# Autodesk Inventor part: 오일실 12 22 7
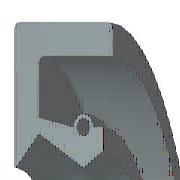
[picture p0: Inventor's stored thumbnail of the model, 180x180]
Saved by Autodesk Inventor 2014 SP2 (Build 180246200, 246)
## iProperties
Created: 2012-02
Part Number: 오일실 12 22 7
Material: 고무
Description: 오일-실
Document SubType Name: Modeling
Standard: KS B 2804
Designer: mduedu
Standards Organization: KS
Language: ko-KR
Size Designation: D - 12 22 7
Categories: <MemberInstance><Categories><Category DisplayName="샤프트 부품" InternalName="7f7aeb1f-a693-4053-b835-cee3144e0d98" Mnemonic="SHFT"><Category DisplayName="실링" Intern
Density: 0.93 g/cm^3
Mass: 1.25383 g
Surface Area: 18.4996 cm^2
Volume: 1.3482 cm^3
Appearance: 고무 - 검은색 - 버전 1.1
IsCustomPart: 1
Author: mduedu
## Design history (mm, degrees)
revolve "본체" stored, may be unused: angle "d17" = 90 deg
revolve "스프링1" stored, may be unused: angle "d18" = 90 deg
body "Solid1"
sketch "스케치1"
  geometry: L1 (0, 11)-(7, 11); L2 (7, 9.25)-(1.75, 9.25); L3 (1.75, 7.75)-(4.9, 6); L4 (4.9, 6)-(0, 6); L5 (0, 0)-(9.586, 0) reference; L6 (4.9, 6)-(6.3, 6.875); L7 (0, 18)-(0, -3) reference; L8 (-1.941, 0)-(11.507, 0) reference; L9 (4.2, 8.1)-(1.75, 8.59); L10 (1.75, 8.59)-(1.75, 9.25); L11 (0, 11)-(0, 6.088); L12 (4.9, 6)-(0, 6); L13 (1.75, 7.75)-(0.152, 6.028); L14 (7, 11)-(7, 9.25); L15 (5.6, 8.1)-(6.3, 8.1); L16 (6.3, 8.1)-(6.3, 6.875); C1 r 0.455 at (4.9, 8.1); A1 r 0.7 centre (4.9, 8.1) between (5.6, 8.1) and (4.2, 8.1); A2 r 0.088 centre (0.088, 6.088) between (0, 6.088) and (0.152, 6.028); 1 further point
  constraints: 28 end point, 5 horizontal alignment, 5 point on line, 4 point on circle, 4 vertical alignment, 3 centre point, 3 tangent, 2 collinear, 2 horizontal, 2 perpendicular, 1 coincident, 1 parallel
  dimensions: "d0" = 22 diameter of L1 L5 (= SD2); "d1" = 1.75 distance of L1.end L2.start (= SD); "d2" = 0.91 diameter of C1 (= SPDI); "d3" = 1.4 diameter of A1 (= SPDA); "d4" = 12 diameter of L3.end L5 (= NND); "d5" = 15.5 diameter of L3.start L5 (= TKDM); "d7" = 17.18 diameter of L9.end L5 (= TKDM + 0.24 x SWDT); "d8" = 1.75 distance between parallel lines of L11 L10 (= SD); "d9" = 4.9 distance from line of L11 C1.centre (= SPDST); "d10" = 16.2 diameter of C1.centre L5 (= HLDM); "d11" = 0.0875 radius of A2 (= 0.25 x LAB); "d12" = 6.3 distance between parallel lines of L11 L16 (= SDI); "d13" = 13.75 diameter of L6.end L5 (= ABDM); "d14" = 7 distance from line of L11 L1.end (= SWDT)
fillet "모깎기1" dims "d6" = 0.3 (= RR)
other parameters: "SD2" = 22 [user parameter; used in 1 equation term], "SWDT" = 7 [user parameter; used in 2 equation terms], "RR" = 0.3 [user parameter; used in 1 equation term], "SD" = 1.75 [user parameter; used in 2 equation terms], "NND" = 12 [user parameter; used in 1 equation term], "SPDA" = 1.4 [user parameter; used in 1 equation term], "SPDI" = 0.91 [user parameter; used in 1 equation term], "TKDM" = 15.5 [user parameter; used in 2 equation terms], "HLDM" = 16.2 [user parameter; used in 1 equation term], "ABDM" = 13.75 [user parameter; used in 1 equation term], "SDI" = 6.3 [user parameter; used in 1 equation term], "SPDST" = 4.9 [user parameter; used in 1 equation term], "LAB" = 0.35 [user parameter; used in 1 equation term], "d15" = 0, "d16" = 0, "d19" = 0
